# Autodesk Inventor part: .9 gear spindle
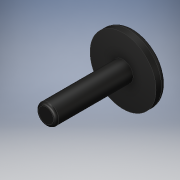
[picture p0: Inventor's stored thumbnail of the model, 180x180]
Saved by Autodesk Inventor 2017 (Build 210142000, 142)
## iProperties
Created: 2017-04
Part Number: .9 gear spindle
Material: Generic
Document SubType Name: Modeling
Designer: Stan
Density: 1 g/cm^3
Appearance: Glossy - Black
Author: Stan
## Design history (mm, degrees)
sketch "Sketch1"
  geometry: C1 r 9.525 at (0, 0); 1 further point
  constraints: 1 centre point, 1 coincident
  dimensions: "d0" = 19.05 diameter of C1
extrude "Extrusion1" new body sketch "Sketch1" distance "d1" = 3.175; taper "d2" = 0 deg
sketch "Sketch2"
  geometry: C1 r 2.921 at (0, 0); 1 further point
  constraints: 1 centre point, 1 coincident
  dimensions: "d3" = 5.842 diameter of C1
extrude "Extrusion2" join sketch "Sketch2" distance "d4" = 22.225; taper "d5" = 0 deg
fillet "Fillet1" dims "d6" = 1.5875
fillet "Fillet2" dims "d7" = 0.79375
body "Solid1"
